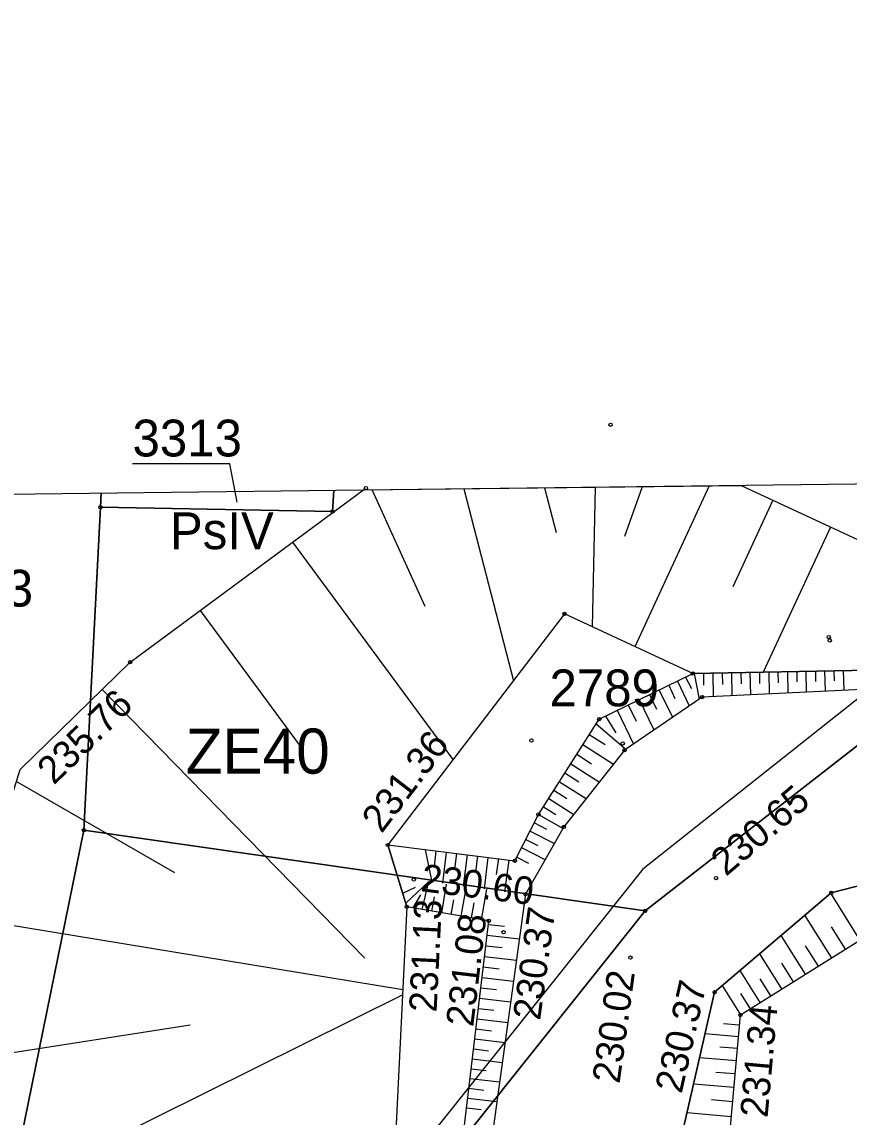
# Model space of a CAD drawing. Extents: x 6596400 to 6597200, y 5539751 to 5540251.
# Drawn here: x 6596725.66 to 6596748.15, y 5540104.16 to 5540133.92 of the extents above; entities that cross this region are included whole.
import ezdxf

# ---------------------------------------------------------------- set-up
doc = ezdxf.new("R2010")
doc.units = 0
for name, color, linetype in [('000 Inne (niezydentyfikowane)', 7, 'Continuous'), ('140-Punkty robocze', 7, 'Continuous'), ('203-punkt graniczny', 7, 'Continuous'), ('209-oznaczenie konturu klasyfikacyjnego', 7, 'Continuous'), ('211-numer działki ewidencyjnej', 7, 'Continuous'), ('217-kontur klasyfikacyjny', 7, 'Continuous'), ('218-kontur użytku gruntowego', 7, 'Continuous'), ('219-działka ewidencyjna', 7, 'Continuous'), ('Linia obszaru zagospodarowania terenu', 7, 'Continuous'), ('Opis obszaru zagospodarowania terenu', 7, 'Continuous'), ('pikieta sztuczna', 7, 'Continuous'), ('pikieta sztuczna-Atr2', 7, 'Continuous'), ('skarpa nieumocniona', 7, 'Continuous'), ('woda płynąca', 7, 'Continuous'), ('Zakres', 7, 'Continuous')]:
    doc.layers.add(name, color=color, linetype=linetype)

# ---------------------------------------------------------------- blocks, each defined once
blk = doc.blocks.new('203')
blk.add_circle((0, 0), 0.045)
blk = doc.blocks.new('PIKIETA')
blk.add_circle((0, 0), 0.045)
blk = doc.blocks.new('PW01')
blk.add_circle((0, 0), 0.045)

msp = doc.modelspace()

# ---------------------------------------------------------------- linework, layer by layer
at = {"layer": '000 Inne (niezydentyfikowane)'}
for p, q in [((6596735.177, 5540121.198), (6596736.61, 5540118.04)), ((6596737.671, 5540121.229), (6596739.02, 5540116.01)), ((6596739.865, 5540121.256), (6596740.18, 5540120.04)), ((6596741.237, 5540121.272), (6596741.16, 5540117.48)), ((6596742.52, 5540121.288), (6596742.04, 5540119.93)), ((6596744.343, 5540121.31), (6596742.32, 5540116.94)), ((6596746.07, 5540120.92), (6596744.98, 5540118.57)), ((6596747.64, 5540120.19), (6596745.81, 5540116.25)), ((6596733.01, 5540119.78), (6596737.37, 5540113.87)), ((6596730.5, 5540117.92), (6596733.19, 5540114.27)), ((6596743.48, 5540116), (6596743.8, 5540115.33)), ((6596743.7, 5540116.11), (6596743.86, 5540115.8)), ((6596743.93, 5540116.21), (6596744.07, 5540115.51)), ((6596744.19, 5540116.22), (6596744.19, 5540115.89)), ((6596744.44, 5540116.22), (6596744.45, 5540115.58)), ((6596744.69, 5540116.22), (6596744.7, 5540115.91)), ((6596744.95, 5540116.23), (6596744.96, 5540115.61)), ((6596745.2, 5540116.23), (6596745.21, 5540115.93)), ((6596745.45, 5540116.24), (6596745.46, 5540115.63)), ((6596745.71, 5540116.24), (6596745.71, 5540115.94)), ((6596745.96, 5540116.25), (6596745.97, 5540115.65)), ((6596746.21, 5540116.25), (6596746.22, 5540115.96)), ((6596746.47, 5540116.26), (6596746.48, 5540115.68)), ((6596746.72, 5540116.26), (6596746.72, 5540115.98)), ((6596746.97, 5540116.27), (6596746.98, 5540115.7)), ((6596747.23, 5540116.27), (6596747.23, 5540115.99)), ((6596747.48, 5540116.28), (6596747.49, 5540115.73)), ((6596747.73, 5540116.28), (6596747.74, 5540116.01)), ((6596747.98, 5540116.29), (6596748, 5540115.75)), ((6596727.84, 5540115.78), (6596734.98, 5540108.47)), ((6596742.98, 5540115.76), (6596743.34, 5540115.02)), ((6596743.24, 5540115.89), (6596743.41, 5540115.53)), ((6596742.44, 5540115.5), (6596742.84, 5540114.68)), ((6596742.72, 5540115.64), (6596742.91, 5540115.24)), ((6596741.84, 5540115.21), (6596742.28, 5540114.29)), ((6596742.14, 5540115.36), (6596742.36, 5540114.92)), ((6596741.27, 5540114.84), (6596742.08, 5540114.15)), ((6596741.52, 5540115.05), (6596741.8, 5540114.6)), ((6596741.08, 5540114.55), (6596741.51, 5540114.28)), ((6596740.91, 5540114.28), (6596741.74, 5540113.75)), ((6596740.74, 5540114.02), (6596741.14, 5540113.76)), ((6596740.58, 5540113.76), (6596741.36, 5540113.26)), ((6596740.42, 5540113.51), (6596740.8, 5540113.27)), ((6596725.51, 5540113.28), (6596729.8, 5540110.8)), ((6596740.12, 5540113.04), (6596740.47, 5540112.81)), ((6596740.27, 5540113.27), (6596741, 5540112.81)), ((6596739.98, 5540112.81), (6596740.66, 5540112.38)), ((6596739.84, 5540112.59), (6596740.17, 5540112.38)), ((6596739.59, 5540112.15), (6596739.92, 5540111.98)), ((6596739.7, 5540112.38), (6596740.37, 5540112)), ((6596739.47, 5540111.93), (6596740.14, 5540111.59)), ((6596739.36, 5540111.7), (6596739.68, 5540111.54)), ((6596736.62, 5540111.42), (6596736.8, 5540110.55)), ((6596736.91, 5540111.39), (6596736.86, 5540110.97)), ((6596737.19, 5540111.35), (6596737.09, 5540110.51)), ((6596737.47, 5540111.32), (6596737.42, 5540110.89)), ((6596737.76, 5540111.28), (6596737.65, 5540110.43)), ((6596738.04, 5540111.25), (6596737.99, 5540110.82)), ((6596739.24, 5540111.48), (6596739.89, 5540111.15)), ((6596738.32, 5540111.21), (6596738.22, 5540110.36)), ((6596738.61, 5540111.18), (6596738.55, 5540110.75)), ((6596738.89, 5540111.14), (6596738.78, 5540110.28)), ((6596739.11, 5540111.22), (6596739.43, 5540111.06)), ((6596736.01, 5540110.24), (6596736.36, 5540110.4)), ((6596736.09, 5540109.97), (6596736.72, 5540110.56)), ((6596736.54, 5540109.8), (6596736.72, 5540110.56)), ((6596737.07, 5540109.71), (6596737.2, 5540110.49)), ((6596737.6, 5540109.62), (6596737.74, 5540110.42)), ((6596738.15, 5540109.52), (6596738.3, 5540110.35)), ((6596736.29, 5540109.84), (6596736.5, 5540110.2)), ((6596736.8, 5540109.75), (6596736.87, 5540110.14)), ((6596737.33, 5540109.66), (6596737.4, 5540110.06)), ((6596737.88, 5540109.57), (6596737.95, 5540109.98)), ((6596724.34, 5540109.54), (6596736.01, 5540107.62)), ((6596738.34, 5540109.39), (6596738.78, 5540109.34)), ((6596738.3, 5540109.1), (6596739.18, 5540109)), ((6596738.27, 5540108.81), (6596738.71, 5540108.76)), ((6596738.23, 5540108.52), (6596739.1, 5540108.42)), ((6596738.2, 5540108.24), (6596738.63, 5540108.18)), ((6596738.13, 5540107.67), (6596738.56, 5540107.62)), ((6596738.17, 5540107.95), (6596739.02, 5540107.85)), ((6596725.5, 5540102.27), (6596736, 5540107.48)), ((6596738.1, 5540107.39), (6596738.94, 5540107.29)), ((6596738.07, 5540107.11), (6596738.49, 5540107.06)), ((6596738.03, 5540106.83), (6596738.87, 5540106.73)), ((6596724.45, 5540105.76), (6596730.23, 5540106.66)), ((6596738, 5540106.55), (6596738.42, 5540106.5)), ((6596737.97, 5540106.28), (6596738.79, 5540106.18)), ((6596737.94, 5540106.01), (6596738.34, 5540105.96)), ((6596737.9, 5540105.74), (6596738.72, 5540105.64)), ((6596737.87, 5540105.47), (6596738.28, 5540105.42)), ((6596737.84, 5540105.2), (6596738.64, 5540105.11)), ((6596737.81, 5540104.94), (6596738.21, 5540104.89)), ((6596737.75, 5540104.41), (6596738.14, 5540104.36)), ((6596737.78, 5540104.67), (6596738.57, 5540104.58))]:
    msp.add_line(p, q, dxfattribs=at)
for points in [[(6596748.44, 5540108.97), (6596747.65, 5540110.24)], [(6596747.67, 5540108.49), (6596746.94, 5540109.64)], [(6596748.05, 5540108.72), (6596747.67, 5540109.33)], [(6596746.96, 5540108.04), (6596746.3, 5540109.09)], [(6596746.32, 5540107.64), (6596745.72, 5540108.59)], [(6596747.31, 5540108.26), (6596746.96, 5540108.81)], [(6596746.63, 5540107.83), (6596746.32, 5540108.34)], [(6596745.73, 5540107.27), (6596745.18, 5540108.14)], [(6596745.2, 5540106.93), (6596744.7, 5540107.73)], [(6596746.02, 5540107.45), (6596745.73, 5540107.91)], [(6596745.46, 5540107.1), (6596745.2, 5540107.51)], [(6596745.16, 5540106.65), (6596744.73, 5540106.69)], [(6596745.14, 5540106.34), (6596744.23, 5540106.42)], [(6596745.11, 5540106.02), (6596744.63, 5540106.06)], [(6596745.08, 5540105.68), (6596744.08, 5540105.77)], [(6596745.05, 5540105.33), (6596744.52, 5540105.37)], [(6596745.01, 5540104.96), (6596743.92, 5540105.05)], [(6596744.98, 5540104.57), (6596744.4, 5540104.62)], [(6596744.94, 5540104.16), (6596743.74, 5540104.27)]]:
    msp.add_lwpolyline(points, dxfattribs=at)
at = {"layer": '211-numer działki ewidencyjnej'}
msp.add_lwpolyline([(6596731.51, 5540120.87), (6596731.31, 5540121.91), (6596728.662, 5540121.91)], dxfattribs=at)
at = {"layer": '217-kontur klasyfikacyjny'}
for points in [[(6596727.814, 5540121.108), (6596727.79, 5540120.73)], [(6596734.1, 5540120.61), (6596734.137, 5540121.185)], [(6596734.137, 5540121.185), (6596734.1, 5540120.61)], [(6596727.79, 5540120.73), (6596727.34, 5540111.95)], [(6596727.79, 5540120.73), (6596734.1, 5540120.61)], [(6596734.1, 5540120.61), (6596727.79, 5540120.73)], [(6596742.6, 5540109.76), (6596752.71, 5540117.63)], [(6596727.34, 5540111.95), (6596742.6, 5540109.76)]]:
    msp.add_lwpolyline(points, dxfattribs=at)
at = {"layer": '218-kontur użytku gruntowego'}
for points in [[(6596727.814, 5540121.108), (6596727.79, 5540120.73)], [(6596727.79, 5540120.73), (6596727.814, 5540121.108)], [(6596734.1, 5540120.61), (6596734.137, 5540121.185)], [(6596734.137, 5540121.185), (6596734.1, 5540120.61)], [(6596727.79, 5540120.73), (6596727.34, 5540111.95)], [(6596727.34, 5540111.95), (6596727.79, 5540120.73)], [(6596727.79, 5540120.73), (6596734.1, 5540120.61)], [(6596734.1, 5540120.61), (6596727.79, 5540120.73)], [(6596742.6, 5540109.76), (6596752.71, 5540117.63)], [(6596752.71, 5540117.63), (6596742.6, 5540109.76)], [(6596727.34, 5540111.95), (6596725.02, 5540100.61)], [(6596725.02, 5540100.61), (6596727.34, 5540111.95)], [(6596727.34, 5540111.95), (6596742.6, 5540109.76)], [(6596742.6, 5540109.76), (6596727.34, 5540111.95)], [(6596742.6, 5540109.76), (6596731.7, 5540096.09)], [(6596731.7, 5540096.09), (6596742.6, 5540109.76)]]:
    msp.add_lwpolyline(points, dxfattribs=at)
at = {"layer": '219-działka ewidencyjna'}
for points in [[(6596727.79, 5540120.73), (6596727.814, 5540121.108)], [(6596734.1, 5540120.61), (6596734.137, 5540121.185)], [(6596727.34, 5540111.95), (6596727.79, 5540120.73)], [(6596727.79, 5540120.73), (6596734.1, 5540120.61)], [(6596742.6, 5540109.76), (6596752.71, 5540117.63)], [(6596725.02, 5540100.61), (6596727.34, 5540111.95)], [(6596742.6, 5540109.76), (6596727.34, 5540111.95)], [(6596731.7, 5540096.09), (6596742.6, 5540109.76)]]:
    msp.add_lwpolyline(points, dxfattribs=at)
at = {"layer": 'Linia obszaru zagospodarowania terenu'}
msp.add_lwpolyline([(6596781.725, 5540112.112), (6596780.93, 5540109.34), (6596777.59, 5540106.98), (6596766.77, 5540110.34), (6596752.84, 5540119.06), (6596742.54, 5540110.89), (6596731.18, 5540096.66), (6596730.7, 5540082.79)], dxfattribs=at)
at = {"layer": 'skarpa nieumocniona'}
for points in [[(6596751.79, 5540118.27), (6596760.37, 5540114.69), (6596748.71, 5540116.3), (6596743.9, 5540116.21), (6596740.41, 5540117.83), (6596735.6, 5540111.55), (6596736.12, 5540109.87), (6596735.55, 5540098.25), (6596728.64, 5540097.09), (6596724.81, 5540103.41), (6596724.02, 5540108.52), (6596725.61, 5540113.6), (6596728.6, 5540116.52), (6596734.94, 5540121.2), (6596745.21, 5540121.32)], [(6596751.79, 5540118.27), (6596760.37, 5540114.69), (6596748.71, 5540116.3), (6596743.9, 5540116.21), (6596740.41, 5540117.83), (6596735.6, 5540111.55), (6596736.12, 5540109.87), (6596735.55, 5540098.25), (6596728.64, 5540097.09), (6596724.81, 5540103.41), (6596724.02, 5540108.52), (6596725.61, 5540113.6), (6596728.6, 5540116.52), (6596734.94, 5540121.2), (6596745.21, 5540121.32)], [(6596742.42, 5540096.36), (6596740.92, 5540088.42), (6596741.25, 5540084.94), (6596741.25, 5540084.94), (6596742.75, 5540092.05), (6596743.5, 5540096.22), (6596744.79, 5540102.47), (6596745.19, 5540106.93), (6596748.55, 5540109.04), (6596750.9, 5540110.05), (6596759.79, 5540109.57), (6596764.72, 5540107.7), (6596768.41, 5540103.97), (6596769.44, 5540104.84), (6596765.11, 5540108.34), (6596759.95, 5540110.31), (6596750.9, 5540111.08), (6596747.66, 5540110.25), (6596744.49, 5540107.55), (6596743.6, 5540103.66)], [(6596742.42, 5540096.36), (6596740.92, 5540088.42), (6596741.25, 5540084.94), (6596741.25, 5540084.94), (6596742.75, 5540092.05), (6596743.5, 5540096.22), (6596744.79, 5540102.47), (6596745.19, 5540106.93), (6596748.55, 5540109.04), (6596750.9, 5540110.05), (6596759.79, 5540109.57), (6596764.72, 5540107.7), (6596768.41, 5540103.97), (6596769.44, 5540104.84), (6596765.11, 5540108.34), (6596759.95, 5540110.31), (6596750.9, 5540111.08), (6596747.66, 5540110.25), (6596744.49, 5540107.55), (6596743.6, 5540103.66)]]:
    msp.add_lwpolyline(points, close=True, dxfattribs=at)
for points in [[(6596736.14, 5540074.83), (6596735.19, 5540080.23), (6596735.33, 5540085.41), (6596734.65, 5540089.1), (6596735.44, 5540093.45), (6596735.8, 5540095.62), (6596737, 5540098.15), (6596738.35, 5540109.49), (6596736.12, 5540109.87), (6596735.6, 5540111.55), (6596739.06, 5540111.12), (6596739.7, 5540112.38), (6596741.35, 5540114.97), (6596743.9, 5540116.21), (6596748.71, 5540116.3), (6596760.37, 5540114.69), (6596767.09, 5540112.87), (6596773.08, 5540108.54), (6596778.11, 5540104.44), (6596785.94, 5540101.26), (6596790.69, 5540099.45)], [(6596736.14, 5540074.83), (6596735.19, 5540080.23), (6596735.33, 5540085.41), (6596734.65, 5540089.1), (6596735.44, 5540093.45), (6596735.8, 5540095.62), (6596737, 5540098.15), (6596738.35, 5540109.49), (6596736.12, 5540109.87), (6596735.6, 5540111.55), (6596739.06, 5540111.12), (6596739.7, 5540112.38), (6596741.35, 5540114.97), (6596743.9, 5540116.21), (6596748.71, 5540116.3), (6596760.37, 5540114.69), (6596767.09, 5540112.87), (6596773.08, 5540108.54), (6596778.11, 5540104.44), (6596785.94, 5540101.26), (6596790.69, 5540099.45)], [(6596790.15, 5540098.33), (6596785.05, 5540099.81), (6596777.76, 5540103.71), (6596772.25, 5540107.73), (6596766.79, 5540112.11), (6596760.34, 5540113.97), (6596748.88, 5540115.79), (6596744.15, 5540115.57), (6596742.04, 5540114.13), (6596740.39, 5540112.04), (6596739.35, 5540110.21), (6596737.64, 5540097.87), (6596736.29, 5540093.37), (6596736.04, 5540089.3), (6596736.53, 5540085.88), (6596736.56, 5540080.1), (6596736.48, 5540078.77)], [(6596790.15, 5540098.33), (6596785.05, 5540099.81), (6596777.76, 5540103.71), (6596772.25, 5540107.73), (6596766.79, 5540112.11), (6596760.34, 5540113.97), (6596748.88, 5540115.79), (6596744.15, 5540115.57), (6596742.04, 5540114.13), (6596740.39, 5540112.04), (6596739.35, 5540110.21), (6596737.64, 5540097.87), (6596736.29, 5540093.37), (6596736.04, 5540089.3), (6596736.53, 5540085.88), (6596736.56, 5540080.1), (6596736.48, 5540078.77)]]:
    msp.add_lwpolyline(points, dxfattribs=at)
at = {"layer": 'woda płynąca'}
for points in [[(6596801.146, 5540105.126), (6596800.55, 5540103.15), (6596798.59, 5540101.49), (6596797.54, 5540099.56), (6596796.12, 5540099.28), (6596790.15, 5540098.33), (6596785.05, 5540099.81), (6596777.76, 5540103.71), (6596772.25, 5540107.73), (6596766.79, 5540112.11), (6596760.34, 5540113.97), (6596748.88, 5540115.79), (6596744.15, 5540115.57), (6596742.04, 5540114.13), (6596740.39, 5540112.04), (6596739.35, 5540110.21), (6596737.64, 5540097.87), (6596736.29, 5540093.37), (6596736.04, 5540089.3), (6596736.53, 5540085.88)], [(6596746.88, 5540042.02), (6596743.2, 5540046.89), (6596742.01, 5540050.53), (6596741.65, 5540054.82), (6596742.47, 5540061.97), (6596743.25, 5540066.3), (6596741.68, 5540074.92), (6596740.68, 5540078.45), (6596740.72, 5540079.85), (6596740.91, 5540084.82), (6596741.25, 5540084.94), (6596740.92, 5540088.42), (6596742.42, 5540096.36), (6596743.6, 5540103.66), (6596744.49, 5540107.55), (6596747.66, 5540110.25), (6596750.9, 5540111.08), (6596759.95, 5540110.31), (6596765.11, 5540108.34), (6596769.44, 5540104.84), (6596775.99, 5540100.07), (6596783.39, 5540096.06), (6596790.43, 5540094.51)]]:
    msp.add_lwpolyline(points, dxfattribs=at)
at = {"layer": 'Zakres'}
msp.add_lwpolyline([(6596822.22, 5540097.5), (6596800.39, 5540105.4), (6596755.76, 5540121.45), (6596697.73, 5540120.74), (6596659.35, 5540133.92), (6596647.64, 5540109.28), (6596697.73, 5540077), (6596721.01, 5540057.77), (6596727.72, 5540045.95), (6596731.95, 5540033.61), (6596741.17, 5540031.18), (6596755.59, 5540029.2), (6596757.85, 5540044.22), (6596787.25, 5540055.04), (6596806.3, 5540048.33), (6596813.97, 5540042.6), (6596833.15, 5540068.58), (6596822.3, 5540077.75)], close=True, dxfattribs=at)

# ---------------------------------------------------------------- block references
at = {"layer": '140-Punkty robocze'}
for p in [(6596741.66, 5540122.97), (6596735.01, 5540121.25), (6596740.41, 5540117.83), (6596747.59, 5540117.2), (6596747.62, 5540117.11), (6596728.6, 5540116.52), (6596743.9, 5540116.21), (6596744.15, 5540115.57), (6596741.35, 5540114.97), (6596739.51, 5540114.39), (6596741.99, 5540114.31), (6596742.04, 5540114.13), (6596739.7, 5540112.38), (6596740.39, 5540112.04), (6596735.6, 5540111.55), (6596739.06, 5540111.12), (6596736.31, 5540110.61), (6596744.53, 5540110.65), (6596739.35, 5540110.21), (6596747.66, 5540110.25), (6596736.12, 5540109.87), (6596738.35, 5540109.49), (6596738.75, 5540109.18), (6596742.2, 5540108.49), (6596744.49, 5540107.55), (6596745.19, 5540106.93)]:
    msp.add_blockref('PIKIETA', p, dxfattribs=at)
at = {"layer": '203-punkt graniczny'}
for p in [(6596727.79, 5540120.73), (6596734.1, 5540120.61), (6596727.34, 5540111.95), (6596742.6, 5540109.76)]:
    msp.add_blockref('203', p, dxfattribs=at)
at = {"layer": 'pikieta sztuczna'}
for p in [(6596735.6, 5540111.55), (6596736.31, 5540110.61), (6596744.53, 5540110.65), (6596739.35, 5540110.21), (6596736.12, 5540109.87), (6596738.35, 5540109.49), (6596742.2, 5540108.49), (6596744.49, 5540107.55), (6596745.19, 5540106.93)]:
    msp.add_blockref('PW01', p, dxfattribs=at)

# ---------------------------------------------------------------- texts
at = {"layer": '209-oznaczenie konturu klasyfikacyjnego'}
msp.add_text('PsIV', height=1, dxfattribs=at).set_placement((6596729.68, 5540119.59))
at = {"layer": '211-numer działki ewidencyjnej'}
for s, p in [('3313', (6596728.662, 5540122.11)), ('3052/3', (6596721.87, 5540118.03)), ('2789', (6596740, 5540115.32))]:
    msp.add_text(s, height=1, dxfattribs=at).set_placement(p)
at = {"layer": 'Opis obszaru zagospodarowania terenu'}
msp.add_text('ZE40', height=1.225, dxfattribs=at).set_placement((6596730.11, 5540113.49))
at = {"layer": 'pikieta sztuczna-Atr2'}
for s, rotation, p in [('235.76', 44.321, (6596726.524, 5540113.163)), ('231.36', 52.551, (6596735.435, 5540111.844)), ('230.65', 40.422, (6596744.796, 5540110.679)), ('230.60', 352.916, (6596736.478, 5540110.296)), ('231.13', 87.192, (6596736.929, 5540106.993)), ('230.37', 82.111, (6596739.743, 5540106.767)), ('231.08', 83.211, (6596737.925, 5540106.591)), ('230.02', 82.111, (6596741.903, 5540105.047)), ('230.37', 77.113, (6596743.591, 5540104.773)), ('231.34', 84.875, (6596745.927, 5540104.123))]:
    msp.add_text(s, height=0.75, rotation=rotation, dxfattribs=at).set_placement(p)

doc.saveas('drawing.dxf')
